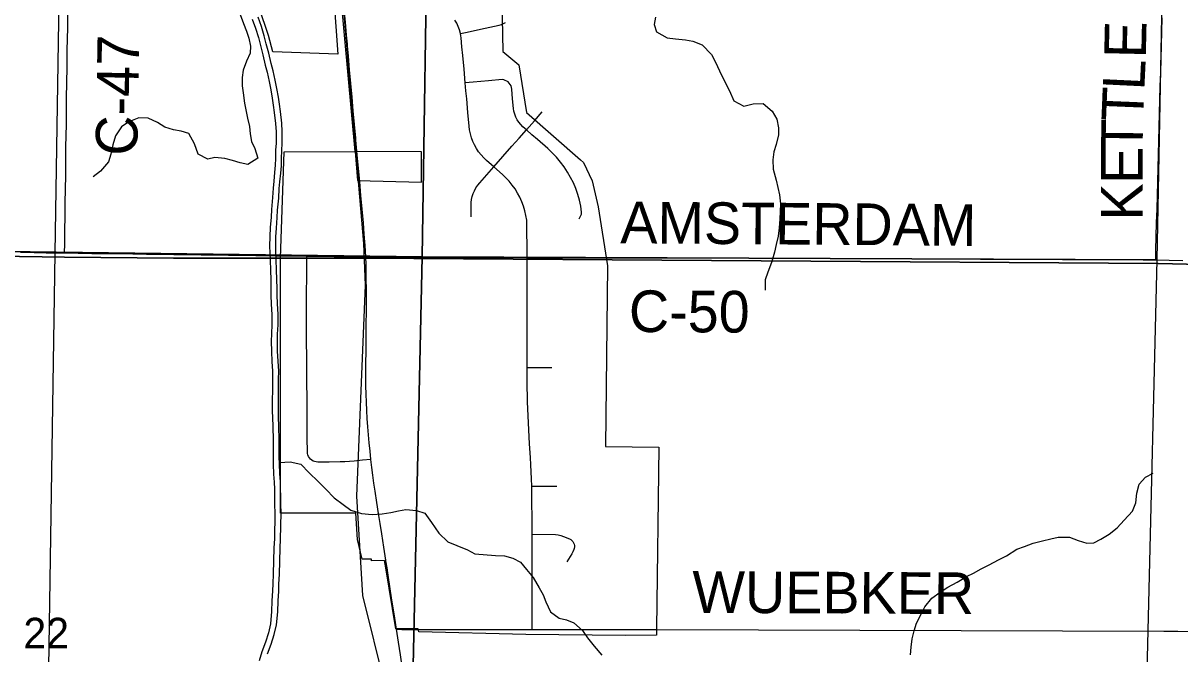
# Model space of a CAD drawing. Extents: x -11.1 to 34, y -3.9 to 22.
# Drawn here: x 4.812 to 6.389, y 14.712 to 15.573 of the extents above; entities that cross this region are included whole.
import ezdxf

# ---------------------------------------------------------------- set-up
doc = ezdxf.new("R2010")
doc.units = 0
for name, color, linetype in [('GM_X_City_Street', 7, 'Continuous'), ('GM_X_Corporation', 7, 'Continuous'), ('GM_X_County_Road', 7, 'Continuous'), ('GM_X_County_Road_Text', 7, 'Continuous'), ('GM_X_Minor_River', 7, 'Continuous'), ('GM_X_Rail_Line', 7, 'Continuous'), ('GM_X_Section_Text', 7, 'Continuous'), ('GM_X_State_Route', 7, 'Continuous'), ('GM_X_Township_Road', 7, 'Continuous'), ('GM_X_Township_Road_Text', 7, 'Continuous')]:
    doc.layers.add(name, color=color, linetype=linetype)

msp = doc.modelspace()

# ---------------------------------------------------------------- linework, layer by layer
at = {"layer": 'GM_X_City_Street'}
for p, q in [((5.4993, 15.1031), (5.533, 15.103)), ((5.5056, 14.9412), (5.5398, 14.9413))]:
    msp.add_line(p, q, dxfattribs=at)
for points in [[(5.5061, 14.7455), (5.5062, 14.8756), (5.5056, 14.9412), (5.5053, 14.9509), (5.5049, 14.9607), (5.5044, 14.9704), (5.5039, 14.9801), (5.5027, 14.9987), (5.5021, 15.0084), (5.5015, 15.0181), (5.501, 15.0276), (5.5005, 15.037), (5.5002, 15.0465), (5.4998, 15.056), (5.4996, 15.0654), (5.4994, 15.0749), (5.4993, 15.1031), (5.4995, 15.2527), (5.4988, 15.3039), (5.4977, 15.3104), (5.4962, 15.3168), (5.4943, 15.3231), (5.492, 15.3292), (5.4893, 15.3352), (5.4862, 15.341), (5.4828, 15.3466), (5.479, 15.3519), (5.4748, 15.357), (5.4703, 15.3618), (5.4656, 15.3663), (5.4538, 15.3767), (5.4439, 15.3854), (5.44, 15.3891), (5.4364, 15.3931), (5.4331, 15.3974), (5.4301, 15.4019), (5.4275, 15.4066), (5.4252, 15.4115), (5.4234, 15.4165), (5.4219, 15.4217), (5.4208, 15.427), (5.4201, 15.4324), (5.4184, 15.4509), (5.4168, 15.4695), (5.4158, 15.4805), (5.4148, 15.4914), (5.4132, 15.51), (5.4115, 15.5285), (5.4104, 15.5405), (5.4094, 15.5525), (5.409, 15.5556), (5.4084, 15.5587), (5.4072, 15.5635), (5.4054, 15.5681), (5.4033, 15.5726), (5.4007, 15.5768)], [(5.4084, 15.5587), (5.4175, 15.5606), (5.4358, 15.5646), (5.4485, 15.5673), (5.4613, 15.57), (5.4643, 15.5709), (5.4672, 15.5722), (5.4699, 15.5738)], [(5.5704, 15.3059), (5.5714, 15.3083), (5.5732, 15.3121), (5.5735, 15.3151), (5.5727, 15.323), (5.5708, 15.3311), (5.5685, 15.3392), (5.5656, 15.3471), (5.5623, 15.3548), (5.5585, 15.3623), (5.5543, 15.3696), (5.5497, 15.3766), (5.5447, 15.3833), (5.5393, 15.3898), (5.5335, 15.3959), (5.5273, 15.4016), (5.5134, 15.4139), (5.5058, 15.4206), (5.4983, 15.4272), (5.4934, 15.4315), (5.4905, 15.4344), (5.4879, 15.4375), (5.4856, 15.441), (5.4838, 15.4447), (5.4823, 15.4485), (5.4813, 15.4525), (5.4807, 15.4565), (5.4795, 15.4697), (5.4784, 15.4828), (5.478, 15.485), (5.4773, 15.4871), (5.4762, 15.4891), (5.4749, 15.4909), (5.4733, 15.4925), (5.4715, 15.4937), (5.4695, 15.4947), (5.4674, 15.4954), (5.4652, 15.4957), (5.4466, 15.4941), (5.4361, 15.4933), (5.4256, 15.4924), (5.4148, 15.4914)], [(5.4228, 15.3087), (5.4229, 15.3183), (5.423, 15.3279), (5.4235, 15.3321), (5.4245, 15.3363), (5.4258, 15.3403), (5.4275, 15.3442), (5.4295, 15.348), (5.4319, 15.3515), (5.4346, 15.3549), (5.4442, 15.3658), (5.4538, 15.3767), (5.4661, 15.3907), (5.4784, 15.4047), (5.4883, 15.4159), (5.4983, 15.4272), (5.5091, 15.4395), (5.5199, 15.4518)], [(5.2861, 14.9774), (5.2748, 14.9764), (5.2634, 14.9753), (5.2571, 14.9747), (5.2508, 14.9743), (5.2444, 14.9741), (5.2292, 14.974), (5.2139, 14.9739), (5.2117, 14.9741), (5.2095, 14.9746), (5.2074, 14.9754), (5.2055, 14.9766), (5.2038, 14.978), (5.2024, 14.9797), (5.2012, 14.9816), (5.2003, 14.9837), (5.1998, 14.9858), (5.1996, 14.9881), (5.1995, 15.0067), (5.1994, 15.0253), (5.1992, 15.044), (5.1991, 15.0626), (5.199, 15.0813), (5.1989, 15.0999), (5.1987, 15.1185), (5.1986, 15.1372), (5.1985, 15.1558), (5.1984, 15.168), (5.1983, 15.1802), (5.1984, 15.1988), (5.1987, 15.2324), (5.1989, 15.2468), (5.199, 15.255)], [(5.5062, 14.8756), (5.5379, 14.8754), (5.5417, 14.8748), (5.5454, 14.8739), (5.549, 14.8726), (5.557, 14.8691), (5.5587, 14.8682), (5.5603, 14.867), (5.5616, 14.8656), (5.5626, 14.8639), (5.5634, 14.8621), (5.5638, 14.8602), (5.5639, 14.8583), (5.5636, 14.8563), (5.5631, 14.8545), (5.5617, 14.8515), (5.5601, 14.8486), (5.5534, 14.8378)]]:
    msp.add_lwpolyline(points, dxfattribs=at)
at = {"layer": 'GM_X_Corporation'}
for points in [[(2.1, 18.3243), (2.1, 15.3106), (2.171, 15.3082), (2.3479, 15.3077), (2.7781, 15.2969), (3.0179, 15.2909), (3.2754, 15.2855), (3.2832, 15.2853), (3.3566, 15.2846), (3.8581, 15.2731), (4.4622, 15.2602), (4.4824, 15.2598), (4.6334, 15.2569), (4.6407, 15.2568), (4.6535, 15.2566), (4.8684, 15.2535), (5.0169, 15.252), (5.2769, 15.2522), (6.3599, 15.2448), (7.3508, 15.2219)], [(5.2356, 15.6062), (5.241, 15.5306), (5.1525, 15.5336), (5.1467, 15.5557), (5.0813, 15.7504)], [(5.4648, 15.6027), (5.4661, 15.534), (5.4879, 15.5158), (5.4984, 15.4507), (5.5721, 15.3862), (5.576, 15.3827), (5.5881, 15.3577), (5.5962, 15.3223), (5.6089, 15.2415), (5.6061, 14.9954), (5.6789, 14.9941), (5.6758, 14.747), (5.6758, 14.7378), (5.633, 14.7374), (5.4977, 14.7388), (5.3514, 14.7426), (5.3508, 14.7467), (5.3468, 14.7467), (5.3203, 14.7467), (5.3065, 14.8299), (5.3048, 14.8397), (5.2871, 14.8394), (5.2869, 14.8417), (5.2742, 14.8417), (5.268, 14.8683), (5.2655, 14.9042), (5.1627, 14.9042), (5.1627, 15.2521), (5.1681, 15.3974), (5.2646, 15.3975), (5.2681, 15.3582), (5.3552, 15.356), (5.3552, 15.3974), (5.2646, 15.3977), (5.2458, 15.6062)], [(7.3508, 15.2219), (6.3599, 15.2448), (5.2769, 15.2522), (5.0169, 15.252), (4.8684, 15.2535), (4.6535, 15.2566), (4.6407, 15.2568), (4.6334, 15.2569), (4.4824, 15.2598), (4.4622, 15.2602), (3.8581, 15.2731), (3.3566, 15.2846), (3.2832, 15.2853), (3.2754, 15.2855), (3.0179, 15.2909), (2.7781, 15.2969), (2.3479, 15.3077), (2.171, 15.3082), (2.1, 15.3106), (2.1, 14.1), (7.332, 14.1)]]:
    msp.add_lwpolyline(points, dxfattribs=at)
for points in [[(4.3746, 16.2728), (5.3715, 16.2638), (5.3559, 15.2538), (4.3579, 15.2669)], [(5.3715, 16.2638), (6.3775, 16.2691), (6.3578, 15.2497), (5.3559, 15.2538)], [(5.3559, 15.2538), (5.3338, 14.242), (4.3335, 14.2541), (4.3579, 15.2669)], [(5.3559, 15.2538), (6.3578, 15.2497), (6.3333, 14.2384), (5.3338, 14.242)]]:
    msp.add_lwpolyline(points, close=True, dxfattribs=at)
at = {"layer": 'GM_X_County_Road'}
for p, q in [((5.6136, 15.2525), (5.8641, 15.2521)), ((5.3471, 14.7456), (5.3995, 14.7455)), ((5.6704, 14.7454), (5.6764, 14.7454))]:
    msp.add_line(p, q, dxfattribs=at)
for points in [[(4.8684, 15.2592), (4.8686, 15.2716), (4.8689, 15.2902), (4.8692, 15.3089), (4.8695, 15.3275), (4.8698, 15.3461), (4.87, 15.3648), (4.8703, 15.3834), (4.8704, 15.4034), (4.8709, 15.4351), (4.8713, 15.4707), (4.8718, 15.5123), (4.872, 15.5352), (4.8727, 15.567), (4.8731, 15.6029), (4.8736, 15.6356), (4.8741, 15.6667), (4.8745, 15.7), (4.8748, 15.7286), (4.8749, 15.7432)], [(4.8082, 15.2601), (4.8268, 15.2598), (4.8433, 15.2596), (4.8597, 15.2593), (4.8684, 15.2592)], [(4.8684, 15.2592), (4.8871, 15.259), (4.9057, 15.2587), (4.9244, 15.2585), (4.943, 15.2583), (4.9616, 15.258), (4.9803, 15.2578), (4.9989, 15.2575), (5.0176, 15.2573), (5.0362, 15.2571), (5.0548, 15.2568), (5.0735, 15.2566), (5.0921, 15.2563), (5.1108, 15.2561), (5.1294, 15.2559), (5.148, 15.2556), (5.1576, 15.2555), (5.1672, 15.2554)], [(5.1672, 15.2554), (5.1831, 15.2552), (5.199, 15.255), (5.2176, 15.2547), (5.2363, 15.2545), (5.2549, 15.2542), (5.267, 15.2541), (5.2794, 15.2539), (5.2981, 15.2537), (5.3167, 15.2534), (5.3354, 15.2532), (5.3465, 15.2531), (5.3577, 15.2529), (5.4995, 15.2527), (5.6136, 15.2525)], [(5.8641, 15.2521), (5.8751, 15.2521), (5.8937, 15.252), (5.9124, 15.2519), (5.931, 15.2518), (5.9497, 15.2518), (5.9683, 15.2517), (5.987, 15.2516), (6.0056, 15.2515), (6.0242, 15.2514), (6.0429, 15.2513), (6.0615, 15.2512), (6.0802, 15.2512), (6.0988, 15.2511), (6.1174, 15.251), (6.1361, 15.2509), (6.1547, 15.2508), (6.1734, 15.2507), (6.192, 15.2507), (6.2106, 15.2506), (6.2293, 15.2505), (6.2479, 15.2504), (6.2666, 15.2503), (6.2852, 15.2502), (6.3039, 15.2502), (6.3225, 15.2501), (6.3394, 15.25), (6.3564, 15.2499), (6.375, 15.2494), (6.3936, 15.2489)], [(5.3211, 14.7459), (5.3286, 14.7458), (5.3397, 14.7457), (5.3471, 14.7456)], [(5.3995, 14.7455), (5.5061, 14.7455), (5.6704, 14.7454)], [(5.6764, 14.7454), (6.3677, 14.7435), (6.3864, 14.7431), (6.405, 14.7427)]]:
    msp.add_lwpolyline(points, dxfattribs=at)
at = {"layer": 'GM_X_Minor_River'}
for points in [[(5.1065, 15.5883), (5.1123, 15.5722), (5.1166, 15.5618), (5.1198, 15.5522), (5.1222, 15.5415), (5.1216, 15.532), (5.1164, 15.5207), (5.112, 15.5087), (5.1106, 15.4984), (5.1108, 15.4874), (5.1121, 15.4775), (5.114, 15.4637), (5.1181, 15.4431), (5.1205, 15.4317), (5.1214, 15.4218), (5.1235, 15.4114), (5.1278, 15.4018), (5.1321, 15.3884), (5.1182, 15.38), (5.108, 15.3822), (5.0975, 15.3854), (5.0869, 15.3883), (5.0733, 15.3894), (5.0638, 15.3874), (5.0507, 15.3941), (5.0457, 15.4083), (5.038, 15.4222), (5.0275, 15.4255), (5.0169, 15.4272), (5.0052, 15.4309), (4.9951, 15.4372), (4.9823, 15.4432), (4.9698, 15.4435), (4.956, 15.4381), (4.946, 15.4315), (4.9378, 15.4192), (4.9341, 15.4067), (4.9315, 15.3939), (4.9283, 15.3837), (4.9174, 15.3706), (4.9073, 15.3633)], [(5.1245, 15.5783), (5.1288, 15.5657), (5.1327, 15.553), (5.1355, 15.5423), (5.139, 15.5297), (5.1421, 15.5156), (5.1446, 15.506), (5.1473, 15.493), (5.1497, 15.4819), (5.1517, 15.4705), (5.153, 15.4609), (5.1543, 15.451), (5.1563, 15.4358), (5.1568, 15.4247), (5.1568, 15.4091), (5.1562, 15.3993), (5.156, 15.3883), (5.1558, 15.3788), (5.1548, 15.3689), (5.1538, 15.3571), (5.1528, 15.3477), (5.1521, 15.3347), (5.1506, 15.3184), (5.15, 15.3082), (5.1489, 15.2938), (5.1483, 15.2816), (5.148, 15.2687), (5.1482, 15.2592), (5.1487, 15.2489), (5.1492, 15.2364), (5.1496, 15.2223), (5.1498, 15.2113), (5.1499, 15.2018), (5.1504, 15.1896), (5.1512, 15.1755), (5.1513, 15.1615), (5.1506, 15.1489), (5.1504, 15.1387), (5.1505, 15.125), (5.1513, 15.1113), (5.1521, 15.098), (5.1519, 15.087), (5.152, 15.0763), (5.1515, 15.0543)], [(5.16, 15.0541), (5.1604, 15.0763), (5.1603, 15.0869), (5.1606, 15.0981), (5.1597, 15.1118), (5.1589, 15.1253), (5.1588, 15.1386), (5.159, 15.1486), (5.1597, 15.1613), (5.1596, 15.1758), (5.1588, 15.19), (5.1583, 15.202), (5.1582, 15.2114), (5.158, 15.2225), (5.1576, 15.2367), (5.1571, 15.2493), (5.1566, 15.2595), (5.1564, 15.2687), (5.1567, 15.2813), (5.1573, 15.2932), (5.1584, 15.3076), (5.159, 15.3178), (5.1605, 15.3341), (5.1612, 15.347), (5.1621, 15.3563), (5.1632, 15.3681), (5.1642, 15.3782), (5.1644, 15.3881), (5.1646, 15.3989), (5.1652, 15.4089), (5.1652, 15.4249), (5.1647, 15.4365), (5.1627, 15.4521), (5.1614, 15.4621), (5.16, 15.4718), (5.158, 15.4836), (5.1555, 15.4948), (5.1528, 15.5079), (5.1503, 15.5175), (5.1472, 15.5317), (5.1436, 15.5445), (5.1408, 15.5553), (5.1368, 15.5683), (5.1326, 15.5808)], [(5.6741, 15.5807), (5.6727, 15.5708), (5.6755, 15.5609), (5.6901, 15.5529), (5.7014, 15.5515), (5.7151, 15.55), (5.7253, 15.5482), (5.738, 15.5433), (5.7506, 15.5301), (5.756, 15.5197), (5.7614, 15.5077), (5.7679, 15.4946), (5.7751, 15.4804)], [(5.7751, 15.4804), (5.7812, 15.4666), (5.7946, 15.4594), (5.8076, 15.4625), (5.8213, 15.4632), (5.8335, 15.4527), (5.8397, 15.4419), (5.8421, 15.43), (5.8422, 15.4205), (5.8388, 15.4073), (5.8359, 15.3971), (5.8345, 15.3862), (5.8349, 15.3736), (5.8387, 15.3587), (5.8411, 15.3484), (5.8435, 15.3385), (5.8447, 15.3263), (5.8444, 15.316), (5.8437, 15.3054), (5.8431, 15.2933), (5.8416, 15.2823), (5.839, 15.2706), (5.8365, 15.2604), (5.8327, 15.2461), (5.8274, 15.2329), (5.8237, 15.2224), (5.8238, 15.2083)], [(5.1515, 15.0543), (5.1517, 15.0444), (5.1518, 15.0341), (5.1524, 15.0235), (5.1527, 15.003), (5.1528, 14.9931), (5.1529, 14.9809), (5.1531, 14.971), (5.1535, 14.9577), (5.1544, 14.9467), (5.1546, 14.9368), (5.1548, 14.9273), (5.1549, 14.9159), (5.1554, 14.9045), (5.1546, 14.8692), (5.1539, 14.857), (5.1531, 14.8213), (5.1524, 14.8077), (5.1522, 14.7982), (5.1512, 14.7849), (5.1508, 14.7701), (5.1493, 14.7534), (5.1464, 14.741), (5.1423, 14.7281), (5.1374, 14.715), (5.1338, 14.7029)], [(5.1454, 14.7123), (5.1502, 14.7254), (5.1545, 14.7387), (5.1576, 14.7521), (5.1592, 14.7696), (5.1596, 14.7845), (5.1606, 14.7978), (5.1608, 14.8074), (5.1615, 14.821), (5.1623, 14.8567), (5.163, 14.8689), (5.1638, 14.9046), (5.1633, 14.9161), (5.1632, 14.9274), (5.163, 14.9369), (5.1628, 14.9471), (5.1619, 14.9582), (5.1615, 14.9712), (5.1613, 14.981), (5.1612, 14.9932), (5.1611, 15.0031), (5.1608, 15.0238), (5.1603, 15.0344), (5.1601, 15.0445), (5.16, 15.0541)], [(5.1615, 14.9736), (5.1763, 14.9743), (5.1906, 14.9709), (5.2021, 14.9593), (5.2144, 14.9476), (5.2248, 14.9371), (5.2363, 14.925), (5.2486, 14.916), (5.259, 14.9082), (5.2733, 14.9037), (5.2881, 14.9025), (5.3014, 14.9034), (5.3132, 14.9054), (5.3239, 14.9074), (5.3338, 14.9091), (5.3482, 14.908), (5.3598, 14.9043), (5.3687, 14.8916), (5.3789, 14.8769), (5.3912, 14.8652), (5.4036, 14.8603), (5.4179, 14.8543), (5.428, 14.8488)], [(6.3339, 14.9437), (6.3425, 14.9533), (6.3529, 14.9587)], [(6.022, 14.7111), (6.023, 14.7213), (6.0245, 14.7327), (6.027, 14.7436), (6.0303, 14.7542), (6.0364, 14.7665), (6.0415, 14.7763), (6.0513, 14.7882), (6.0626, 14.7966), (6.073, 14.8032), (6.0857, 14.81), (6.0984, 14.8181), (6.108, 14.8224), (6.1184, 14.8282), (6.1292, 14.8336), (6.1419, 14.8405), (6.153, 14.8462), (6.1669, 14.855), (6.1776, 14.8589), (6.1895, 14.8635), (6.2021, 14.8666), (6.2132, 14.8693), (6.2235, 14.8714), (6.2387, 14.8717), (6.2507, 14.8669), (6.2624, 14.8635), (6.2719, 14.864), (6.2818, 14.8687), (6.293, 14.8756), (6.3039, 14.8844), (6.3136, 14.8948), (6.325, 14.9071), (6.3294, 14.9183), (6.3305, 14.9316), (6.3339, 14.9437)], [(5.428, 14.8488), (5.4561, 14.8466), (5.4686, 14.8459), (5.4799, 14.8429), (5.49, 14.8374), (5.4985, 14.8273), (5.5073, 14.8164), (5.5157, 14.8025), (5.5211, 14.7929), (5.5246, 14.7833), (5.5311, 14.7699), (5.543, 14.7612), (5.5528, 14.7587), (5.563, 14.7546), (5.5748, 14.744), (5.5814, 14.7344), (5.5906, 14.7228), (5.6009, 14.7107)]]:
    msp.add_lwpolyline(points, dxfattribs=at)
at = {"layer": 'GM_X_Rail_Line'}
for points in [[(4.8375, 14.1), (4.84, 14.2474), (4.8556, 15.259), (4.8714, 16.2666), (4.8783, 16.7081), (4.896, 17.8593), (4.8941, 17.9315), (4.8895, 17.9844), (4.8767, 18.0419), (4.6837, 18.6752), (4.6608, 18.751), (4.6471, 18.7984), (4.6397, 18.855), (4.6467, 19.2877), (4.6769, 20.631), (4.6804, 20.8229), (4.6818, 20.9)], [(4.878, 16.7078), (4.9266, 16.6377), (4.9294, 16.6149), (5.0609, 16.6122), (5.0598, 16.4614), (5.059, 16.2648), (5.1889, 16.2589), (5.2287, 15.8244), (5.2761, 15.2722), (5.2785, 15.2153), (5.2666, 14.9275), (5.2749, 14.792), (5.3053, 14.6694), (5.3278, 14.6319)]]:
    msp.add_lwpolyline(points, dxfattribs=at)
at = {"layer": 'GM_X_State_Route'}
msp.add_line((5.2541, 15.5439), (5.253, 15.5562), dxfattribs=at)
for points in [[(5.253, 15.5562), (5.2514, 15.5742), (5.2498, 15.5923), (5.2481, 15.6109), (5.247, 15.6236)], [(5.2658, 15.4132), (5.2655, 15.4161), (5.2638, 15.4347), (5.2622, 15.4533), (5.2605, 15.4718), (5.2589, 15.4904), (5.2572, 15.509), (5.2556, 15.5275), (5.2543, 15.5419), (5.2541, 15.5439)], [(5.2794, 15.2539), (5.2782, 15.2694), (5.2772, 15.2849), (5.2759, 15.3004), (5.2742, 15.319), (5.2726, 15.3376), (5.2709, 15.3561), (5.2692, 15.3747), (5.2676, 15.3933), (5.2667, 15.4032), (5.2658, 15.4132)], [(5.3065, 14.8403), (5.3038, 14.8577), (5.3009, 14.8762), (5.2988, 14.89), (5.2966, 14.9038), (5.2943, 14.919), (5.2919, 14.9341), (5.2904, 14.945), (5.2888, 14.9559), (5.2875, 14.9667), (5.2861, 14.9774), (5.285, 14.9887), (5.2838, 15), (5.2829, 15.0111), (5.282, 15.0222), (5.2813, 15.0334), (5.2806, 15.0445), (5.2801, 15.0556), (5.2797, 15.0668), (5.2795, 15.0779), (5.2792, 15.0891), (5.2794, 15.1077), (5.2796, 15.1263), (5.2797, 15.145), (5.2799, 15.1636), (5.28, 15.1779), (5.2801, 15.1921), (5.28, 15.2108), (5.2799, 15.222), (5.2798, 15.2333), (5.2796, 15.2436), (5.2794, 15.2539)], [(5.3211, 14.7459), (5.3182, 14.7643), (5.3154, 14.7828), (5.3125, 14.8012), (5.3097, 14.8196), (5.3082, 14.8295), (5.3066, 14.8393), (5.3065, 14.8403)], [(5.3415, 14.5069), (5.3417, 14.5183), (5.342, 14.5306), (5.3418, 14.5416), (5.3417, 14.5525), (5.3413, 14.5635), (5.3409, 14.5744), (5.3404, 14.5853), (5.3398, 14.5962), (5.339, 14.6072), (5.3382, 14.6181), (5.3371, 14.629), (5.3361, 14.6399), (5.3349, 14.6507), (5.3336, 14.6616), (5.3321, 14.6724), (5.3307, 14.6833), (5.3293, 14.6925), (5.3265, 14.711), (5.3238, 14.7284), (5.3211, 14.7459)]]:
    msp.add_lwpolyline(points, dxfattribs=at)
at = {"layer": 'GM_X_Township_Road'}
msp.add_lwpolyline([(6.3564, 15.2499), (6.3567, 15.2631), (6.3572, 15.2817), (6.3577, 15.3004), (6.3582, 15.319), (6.3587, 15.3376), (6.3592, 15.3563), (6.3597, 15.3749), (6.3602, 15.3935), (6.3607, 15.4122), (6.3612, 15.4308), (6.3617, 15.4494), (6.3622, 15.4681), (6.3627, 15.4867), (6.3632, 15.5053), (6.3637, 15.524), (6.3642, 15.5426), (6.3647, 15.5613), (6.3652, 15.5799)], dxfattribs=at)

# ---------------------------------------------------------------- texts
at = {"layer": 'GM_X_County_Road_Text'}
for s, rotation, p in [('C-47', 89.023, (4.9675, 15.3915)), ('AMSTERDAM', 359.5692, (5.6262, 15.2725)), ('C-50', 359.6571, (5.6379, 15.1515)), ('WUEBKER', 359.722, (5.7245, 14.7684))]:
    msp.add_text(s, height=0.05682, rotation=rotation, dxfattribs=at).set_placement(p)
at = {"layer": 'GM_X_Section_Text'}
msp.add_text('22', height=0.04186, rotation=0, dxfattribs=at).set_placement((4.8123, 14.7197))
at = {"layer": 'GM_X_Township_Road_Text'}
for s, rotation, p in [('E', 88.7202, (6.3429, 15.5243)), ('L', 87.254, (6.3408, 15.4803)), ('T', 87.6422, (6.3391, 15.4379)), ('T', 89.3164, (6.3386, 15.3958)), ('E', 89.9764, (6.3385, 15.3535)), ('K', 90, (6.3385, 15.3035))]:
    msp.add_text(s, height=0.0568, rotation=rotation, dxfattribs=at).set_placement(p)

doc.saveas('drawing.dxf')
